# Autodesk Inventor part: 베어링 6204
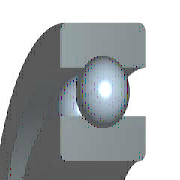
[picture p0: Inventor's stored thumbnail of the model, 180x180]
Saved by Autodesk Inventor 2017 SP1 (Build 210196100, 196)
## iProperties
IsCustomPart: 0
Created: 2018-09
Part Number: 베어링 6204
Material: 스테인리스강
Description: 깊은 그루브 볼 베어링
Document SubType Name: Modeling
Standard: KS B 2023
Standards Organization: KS
Language: ko-KR
Size Designation: 6204 - 20 x 47 x 14
Categories: <MemberInstance><Categories><Category DisplayName="샤프트 부품" InternalName="7f7aeb1f-a693-4053-b835-cee3144e0d98" Mnemonic="SHFT"><Category DisplayName="베어링" Inter
Density: 8.08 g/cm^3
Mass: 107.173 g
Surface Area: 87.8912 cm^2
Volume: 13.264 cm^3
Appearance: 노란색
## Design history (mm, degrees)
sketch "스케치" dims "d0" = 7.02 (= -0.26 x WD + 0.26 x BD)
  geometry: L1 (3.49, 16.75)-(10.51, 16.75); L2 (7, 16.75)-(7, 13.24); L3 (7, 16.75)-(7, 20.26); L4 (4.392, 14.401)-(0, 14.401); L5 (0, 10)-(14, 10); L6 (4.392, 19.099)-(0, 19.099); L7 (0, 23.5)-(14, 23.5); L8 (14, 10)-(14, 14.401); L9 (9.608, 14.401)-(14, 14.401); L10 (9.608, 19.099)-(14, 19.099); L11 (14, 23.5)-(14, 19.099); L12 (-1.4, 0)-(8.4, 0) reference; L13 (0, -0.3)-(0, 5.3) reference
  constraints: 22 end point, 4 point on line, 2 collinear, 2 perpendicular, 2 symmetric about line, 1 midpoint, 1 parallel, 14 other
  dimensions: "d9" = 20 diameter of L5 L12 (= WD); "d11" = 47 diameter of L7 L12 (= BD); "d12" = 14 distance between parallel lines of L8 L13 (= KB); "d13" = 28.802 diameter of L9 L12 (= 0.326 x BD + 0.674 x WD)
revolve "본체" stored, may be unused: angle "d6" = 90 deg
revolve "볼" stored, may be unused: angle "d7" = 90 deg
pattern_circular "IDS_ARRAYBALL[SIMPL:T]" dims angle "d3" = 360 deg
body "Solid1"
fillet "모깎기1" dims "d1" = 1 (= KRS)
other parameters: "WD" = 20 [user parameter; used in 5 equation terms], "BD" = 47 [user parameter; used in 5 equation terms], "KB" = 14 [user parameter; used in 1 equation term], "KRS" = 1 [user parameter; used in 1 equation term], "d4" = 0, "d5" = 0, "d8" = 0, "d14" = 0, "d15" = 0, "BBA" = 0 [user parameter], "BC0" = 6550000 [user parameter], "BC" = 1.27e+07 [user parameter], "BR" = 23.5 (= 0.5 x BD) [user parameter]
